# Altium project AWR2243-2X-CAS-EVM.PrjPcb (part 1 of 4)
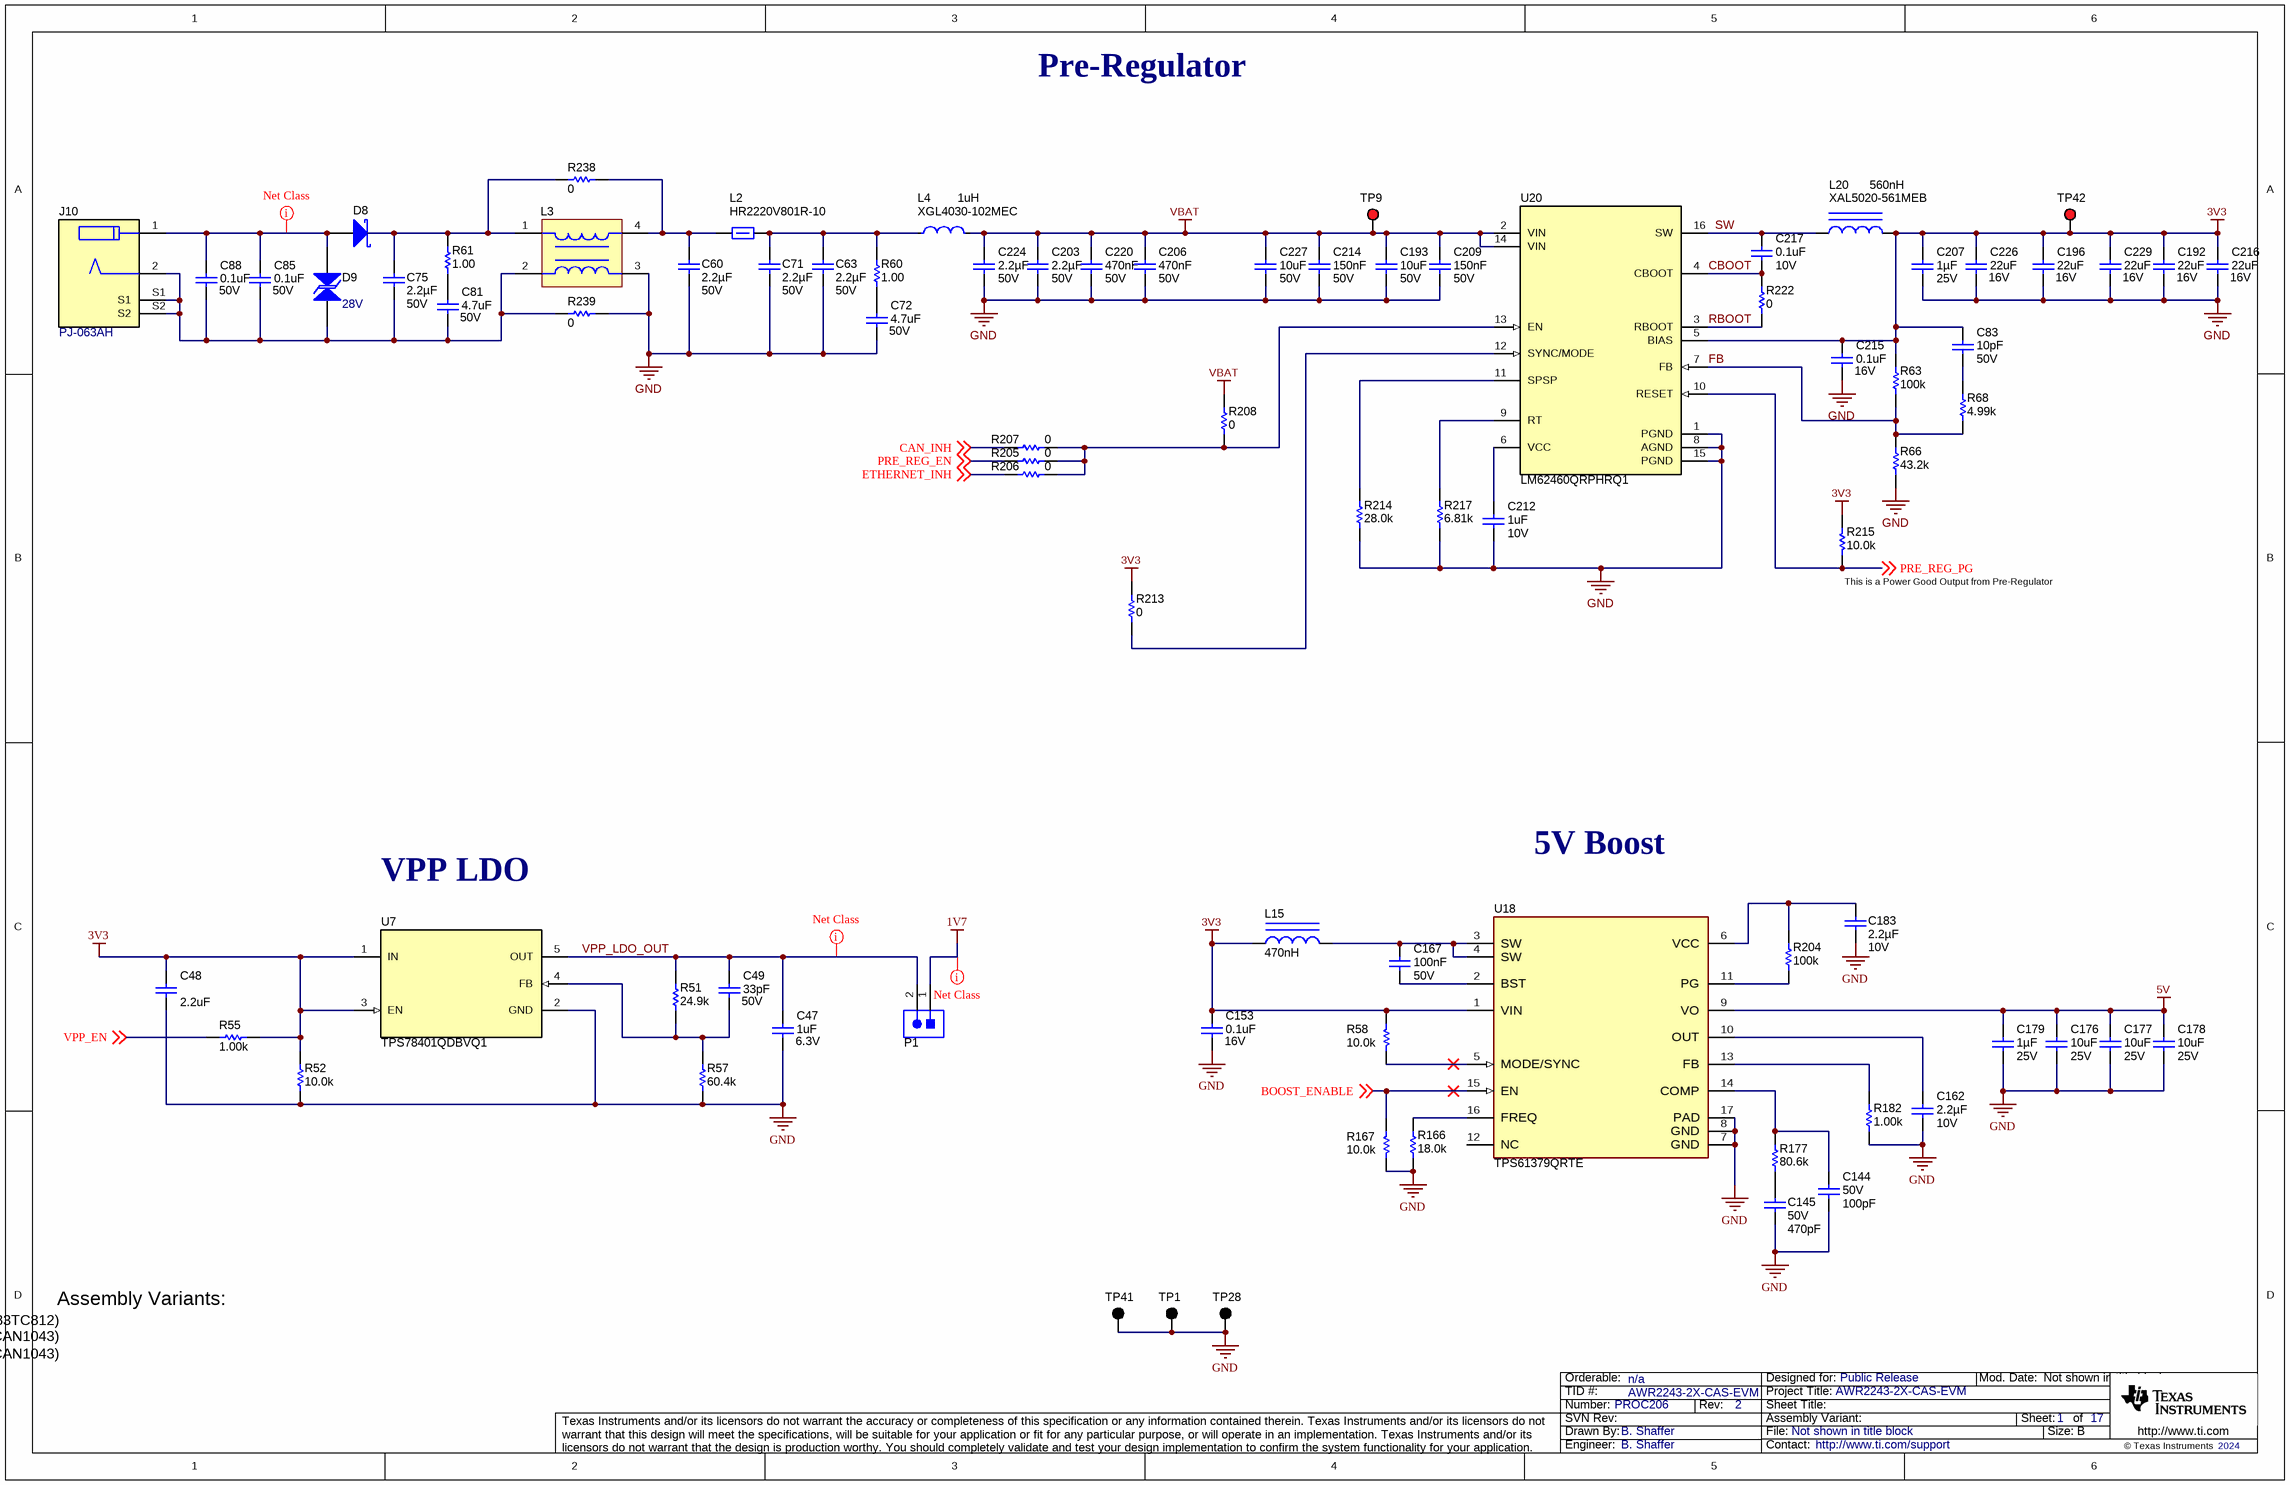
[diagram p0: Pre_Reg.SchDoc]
CopyrightYear: 2024; EVM_orderable: n/a; PCB_Layout: Krypton Solutions; PCB_Rev: C; PRJ_Customer: Public Release; PRJ_Engineer: B. Shaffer; PRJ_Number: PROC206; PRJ_Title: AWR2243-2X-CAS-EVM; SCH_Rev: 2; TechSupport: http://www.ti.com/support; TID: AWR2243-2X-CAS-EVM
17 sheets, 637 parts. Net scope: global (net labels, ports and power ports of the same name join across sheets).
Board file: AWR2243-2X-CAS-EVM.PcbDoc
Sheets:
  Pre_Reg.SchDoc
  PMIC.schdoc
  SOC_PWR.SchDoc
  SOC_IO.schdoc
  SOC_FLASH_SOP.SchDoc
  FE1_PWR.SchDoc
  FE1_IO.schdoc
  FE2_PWR.SchDoc
  FE2_IO.schdoc
  2CAN.SchDoc
  Enet_PHY.SchDoc
  Enet_Conn.SchDoc
  Temp.schdoc
  Connectors.schdoc
  Clock_Buff.SchDoc
  XDS110.schdoc
  Hardware.SchDoc

## Sheet Pre_Reg.SchDoc
size 431 x 279 mm; Date: Not shown in title block; ApprovedBy: Not shown in title block; CheckedBy: Not shown in title block; Author: Not shown in title block; CompanyName: Not shown in title block; DrawnBy: B. Shaffer; Engineer: Not shown in title block; Organization: Not shown in title block; Address1: Not shown in title block; Address2: Not shown in title block; Address3: Not shown in title block; Address4: Not shown in title block; DocumentNumber: 1; Revision: Use project parameter SCH_Rev; SheetNumber: 1; SheetTotal: 17; PageSetup: Record=PageOptions¦CenterHorizontal=True¦CenterVertical=True¦PrintScale=1.00¦XCorrection=1.00¦YCorrection=1.00¦PrintKind=0¦BorderSize=5000000¦LeftOffset=0¦BottomOffset=0¦Orientation=2¦PaperLength=1000¦PaperWidth=1000¦Scale=100¦PaperSource=15¦PrintQuality=600¦MediaType=1¦DitherType=10¦PaperKind=Letter¦PrintScaleMode=1

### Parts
C47  VDC_V: 6.3V  ValueDisplayed: 1uF  [0402]  (hidden comment: GRM155R70J105MA12D)
C48  ValueDisplayed: 2.2uF  [0402_065L]  (hidden comment: C1005X7S1A225K050BC)
C49  VDC_V: 50V  ValueDisplayed: 33pF  [0402L]  (hidden comment: C0402C330J5GAC)
C60  Cap_F: 2.2µF  VDC_V: 50V  [0805_HV]  (hidden comment: CGA4J3X7R1H225K125AB)
C63  Cap_F: 2.2µF  VDC_V: 50V  [0805_HV]  (hidden comment: CGA4J3X7R1H225K125AB)
C71  Cap_F: 2.2µF  VDC_V: 50V  [0805_HV]  (hidden comment: CGA4J3X7R1H225K125AB)
C72  VDC_V: 50V  ValueDisplayed: 4.7uF  [1206_180]  (hidden comment: C3216X7R1H475K160AC)
C75  Cap_F: 2.2µF  VDC_V: 50V  [0805_HV]  (hidden comment: CGA4J3X7R1H225K125AB)
C81  VDC_V: 50V  ValueDisplayed: 4.7uF  [1206_180]  (hidden comment: C3216X7R1H475K160AC)
C83  VDC_V: 50V  ValueDisplayed: 10pF  [0603]  (hidden comment: CGA3E2C0G1H100D080AA)
C85  VDC_V: 50V  ValueDisplayed: 0.1uF  [0603]  (hidden comment: CGA3E3X8R1H104K080AB)
C88  VDC_V: 50V  ValueDisplayed: 0.1uF  [0603]  (hidden comment: CGA3E3X8R1H104K080AB)
C144  VDC_V: 50V  ValueDisplayed: 100pF  [0402]  (hidden comment: 885012205055)
C145  VDC_V: 50V  ValueDisplayed: 470pF  [0402]  (hidden comment: GRM155R71H471KA01D)
C153  VDC_V: 16V  ValueDisplayed: 0.1uF  [0402L]  (hidden comment: GCM155R71C104KA55D)
C162  Cap_F: 2.2µF  VDC_V: 10V  [0603]  (hidden comment: GRM188R71A225KE15J)
C167  Cap_F: 100nF  VDC_V: 50V  [0603L]  (hidden comment: GCM188R71H104KA57D)
C176  VDC_V: 25V  ValueDisplayed: 10uF  [1210_280]  (hidden comment: GCM32ER71E106KA57L)
C177  VDC_V: 25V  ValueDisplayed: 10uF  [1210_280]  (hidden comment: GCM32ER71E106KA57L)
C178  VDC_V: 25V  ValueDisplayed: 10uF  [1210_280]  (hidden comment: GCM32ER71E106KA57L)
C179  Cap_F: 1µF  VDC_V: 25V  [0603L]  (hidden comment: GCM188R71E105KA64D)
C183  Cap_F: 2.2µF  VDC_V: 10V  [0603]  (hidden comment: GRM188R71A225KE15J)
C192  VDC_V: 16V  ValueDisplayed: 22uF  [1210_280]  (hidden comment: CO4)
C193  VDC_V: 50V  ValueDisplayed: 10uF  [1210_270]  (hidden comment: GRM32ER71H106KA12L)
C196  VDC_V: 16V  ValueDisplayed: 22uF  [1210_280]  (hidden comment: CO2)
C203  Cap_F: 2.2µF  VDC_V: 50V  [0805_HV]  (hidden comment: CGA4J3X7R1H225K125AB)
C206  Cap_F: 470nF  VDC_V: 50V  [0603]  (hidden comment: CGA3E3X7R1H474K080AE)
C207  Cap_F: 1µF  VDC_V: 25V  [0805_HV]  (hidden comment: CO5)
C209  Cap_F: 150nF  VDC_V: 50V  [0603]  (hidden comment: C1608X7R1H154K080AB)
C212  VDC_V: 10V  ValueDisplayed: 1uF  [0603]  (hidden comment: CBIAS)
C214  Cap_F: 150nF  VDC_V: 50V  [0603]  (hidden comment: C1608X7R1H154K080AB)
C215  VDC_V: 16V  ValueDisplayed: 0.1uF  [0402L]  (hidden comment: GCM155R71C104KA55D)
C216  VDC_V: 16V  ValueDisplayed: 22uF  [1210_280]  (hidden comment: CO4)
C217  VDC_V: 10V  ValueDisplayed: 0.1uF  [0603L]  (hidden comment: CBOOT)
C220  Cap_F: 470nF  VDC_V: 50V  [0603]  (hidden comment: CGA3E3X7R1H474K080AE)
C224  Cap_F: 2.2µF  VDC_V: 50V  [0805_HV]  (hidden comment: CGA4J3X7R1H225K125AB)
C226  VDC_V: 16V  ValueDisplayed: 22uF  [1210_280]  (hidden comment: CO1)
C227  VDC_V: 50V  ValueDisplayed: 10uF  [1210_270]  (hidden comment: GRM32ER71H106KA12L)
C229  VDC_V: 16V  ValueDisplayed: 22uF  [1210_280]  (hidden comment: CO3)
D8  FSV530AF  [SMAF]  (value not drawn)
D9  value 28V  [SOD-123]  (hidden comment: ATV02W280B-HF)
J10  PJ-063AH  [CUI_PJ-063AH]
L2  HR2220V801R-10  [2220_390]
L3  ACM1211-701-2PL-TL01  [TDK_ACM1211]  (value not drawn)
L4  value 1uH  [FP-XGL4030-102MEC_SMD_IND_4MM0_4MM0-MFG]  (hidden comment: XGL4030-102MEC)
L15  ValueDisplayed: 470nH  [XEL4030_310]  (hidden comment: XEL4030-471MEB)
L20  ValueDisplayed: 560nH  [XAL5020]  (hidden comment: XAL5020-561MEB)
P1  TSW-102-07-G-S  [TSW-102-07-G-S]  (value not drawn)
R51  ValueDisplayed: 24.9k  [0402]  (hidden comment: CRCW040224K9FKED)
R52  ValueDisplayed: 10.0k  [0402]  (hidden comment: ERJ-2RKF1002X)
R55  ValueDisplayed: 1.00k  [0603]  (hidden comment: RFF)
R57  ValueDisplayed: 60.4k  [0402]  (hidden comment: CRCW040260K4FKED)
R58  ValueDisplayed: 10.0k  [0402]  (hidden comment: CRCW040210K0FKED)
R60  ValueDisplayed: 1.00  [0402]  (hidden comment: CRCW04021R00FKED)
R61  ValueDisplayed: 1.00  [0402]  (hidden comment: CRCW04021R00FKED)
R63  ValueDisplayed: 100k  [0402]  (hidden comment: CRCW0402100KFKED)
R66  ValueDisplayed: 43.2k  [0402]  (hidden comment: CRCW040243K2FKED)
R68  ValueDisplayed: 4.99k  [0402]  (hidden comment: CRCW04024K99FKED)
R166  ValueDisplayed: 18.0k  [0402]  (hidden comment: CRCW040218K0FKED)
R167  ValueDisplayed: 10.0k  [0402]  (hidden comment: CRCW040210K0FKED)
R177  ValueDisplayed: 80.6k  [0402]  (hidden comment: CRCW040280K6FKED)
R182  ValueDisplayed: 1.00k  [0402]  (hidden comment: CRCW04021K00FKED)
R204  ValueDisplayed: 100k  [0402]  (hidden comment: CRCW0402100KFKED)
R205  ValueDisplayed: 0  [0402]  (hidden comment: CRCW04020000Z0ED)
R206  ValueDisplayed: 0  [0402]  (hidden comment: CRCW04020000Z0ED)
R207  ValueDisplayed: 0  [0402]  (hidden comment: CRCW04020000Z0ED)
R208  ValueDisplayed: 0  [0402]  (hidden comment: CRCW04020000Z0ED)
R213  ValueDisplayed: 0  [0402]  (hidden comment: CRCW04020000Z0ED)
R214  ValueDisplayed: 28.0k  [0402]  (hidden comment: CRCW040228K0FKED)
R215  ValueDisplayed: 10.0k  [0402]  (hidden comment: CRCW040210K0FKED)
R217  ValueDisplayed: 6.81k  [0402]  (hidden comment: CRCW04026K81FKED)
R222  ValueDisplayed: 0  [0402]  (hidden comment: CRCW04020000Z0ED)
R238  ValueDisplayed: 0  [1206]  (hidden comment: CRCW12060000Z0EAHP)
R239  ValueDisplayed: 0  [1206]  (hidden comment: CRCW12060000Z0EAHP)
TP1  5001  [Keystone5001]  (value not drawn)
TP9  5000  [Keystone5000]  (value not drawn)
TP28  5001  [Keystone5001]  (value not drawn)
TP41  5001  [Keystone5001]  (value not drawn)
TP42  5000  [Keystone5000]  (value not drawn)
U7  TPS78401QDBVQ1  [DBV0005A_N]
U18  TPS61379QRTE  [RTE0016K-MFG]
U20  LM62460QRPHRQ1  [RPH0016A]

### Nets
1V7: P1.1
3V3: C48.2 C83.1 C153.2 C192.1 C196.1 C207.1 C215.2 C216.1 C226.1 C229.1 L15.1 L20.2 R52.2 R55.1 R58.2 R63.2 R213.1 R215.2 TP42.1 U7.1(IN) U7.3(EN) U18.1(VIN) U20.5(BIAS)
5V: C176.1 C177.1 C178.1 C179.1 U18.9(VO)
GND: C47.2 C48.1 C60.2 C63.2 C71.2 C72.2 C144.2 C145.2 C153.1 C162.2 C176.2 C177.2 C178.2 C179.2 C183.2 C192.2 C193.2 C196.2 C203.2 C206.2 C207.2 C209.2 C212.1 C214.2 C215.1 C216.2 C220.2 C224.2 C226.2 C227.2 C229.2 L3.3 R52.1 R57.1 R66.1 R166.1 R167.1 R182.2 R214.1 R217.1 R239.2 TP1.1 TP28.1 TP41.1 U7.2(GND) U18.7(GND) U18.8(GND) U18.17(PAD) U20.1(PGND) U20.8(AGND) U20.15(PGND)
VBAT: C193.1 C203.1 C206.1 C209.1 C214.1 C220.1 C224.1 C227.1 L4.2 R208.1 TP9.1 U20.2(VIN) U20.14(VIN)
BOOST_ENABLE: R167.2 U18.15(EN) ; off-sheet BOOST_ENABLE
CAN_INH: R207.2 ; off-sheet CAN_INH
CBOOT: C217.2 R222.1 U20.4(CBOOT)
ETHERNET_INH: R206.2 ; off-sheet ETHERNET_INH
FB: R63.1 R66.2 R68.1 U20.7(FB)
PRE_REG_EN: R205.2 ; off-sheet PRE_REG_EN
PRE_REG_PG: R215.1 U20.10(RESET) ; off-sheet PRE_REG_PG
RBOOT: R222.2 U20.3(RBOOT)
SW: C217.1 L20.1 U20.16(SW)
VPP_EN: R55.2 ; off-sheet VPP_EN
VPP_LDO_OUT: C47.1 C49.1 P1.2 R51.2 U7.5(OUT)
NetC49_2: C49.2 R51.1 R57.2 U7.4(FB)
NetC60_1: C60.1 L2.1 L3.4 R238.2
NetC63_1: C63.1 C71.1 L2.2 L4.1 R60.2
NetC72_1: C72.1 R60.1
NetC75_1: C75.1 D8.1(K) L3.1 R61.2 R238.1
NetC75_2: C75.2 C81.2 C85.2 C88.2 D9.1 J10.2 J10.S1 J10.S2 L3.2 R239.1
NetC81_1: C81.1 R61.1
NetC83_2: C83.2 R68.2
NetC85_1: C85.1 C88.1 D8.2(A) D9.2 J10.1
NetC144_1: C144.1 R177.2 U18.14(COMP)
NetC145_1: C145.1 R177.1
NetC162_1: C162.1 U18.10(OUT)
NetC167_1: C167.1 L15.2 U18.3(SW) U18.4(SW)
NetC167_2: C167.2 U18.2(BST)
NetC183_1: C183.1 R204.2 U18.6(VCC)
NetC212_2: C212.2 U20.6(VCC)
NetR58_1: R58.1 U18.5(MODE/SYNC)
NetR166_2: R166.2 U18.16(FREQ)
NetR182_1: R182.1 U18.13(FB)
NetR204_1: R204.1 U18.11(PG)
NetR205_1: R205.1 R206.1 R207.1 R208.2 U20.13(EN)
NetR213_2: R213.2 U20.12(SYNC/MODE)
NetR214_2: R214.2 U20.11(SPSP)
NetR217_2: R217.2 U20.9(RT)

Not connected (* = marked no-connect by the designer): U18 12(NC)

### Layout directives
net class PWR: 1V7, NetC85_1, VPP_LDO_OUT

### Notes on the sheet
- Pre-Regulator
- (near R215) This is a Power Good Output from Pre-Regulator
- VPP LDO
- 5V Boost
- Assembly Variants:
- 812: DP83TC812 Ethernet and CAN present.  WAKE Controlled by Ethernet (DP83TC812)
- CAN: DP83TC812 Ethernet and CAN present.  WAKE Controlled by CAN (TCAN1043)
- 811: DP83TC811 Ethernet and CAN present.  WAKE Controlled by CAN (TCAN1043)

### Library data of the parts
C47 = CMP-0006624-2: CAP, CERM, 1 uF, 6.3 V, +/- 20%, X7R, 0402; Manufacturer: MuRata; TaMin_C: -55°C; Polarized: N; SizeAreaWB_mm2: 3; Value1: Unknown; U/M: EA; Value: 1uF; TaMax_C: 125°C; SizeZ_mm: 0.6; SizeX_mm: 1; SizeY_mm: 0.5; CompType: Capacitor; Cap_F: 1µF; AEC Category: Q200
C48 = CMP-0006302-2: CAP, CERM, 2.2 uF, 10 V, +/- 10%, X7S, 0402; Manufacturer: TDK; TaMin_C: -55°C; ESR_ohm: 5.925m; Polarized: N; SizeAreaWB_mm2: 3; Value1: 0.005925 ohm; U/M: EA; Value: 2.2uF; TaMax_C: 125°C; SizeZ_mm: 0.65; SizeX_mm: 1; SizeY_mm: 0.5; Cap_Case: 0402_065; Value2: 10V; CompType: Capacitor; Cap_F: 2.2µF; IRMS_A: 2.05591A; AEC Category: Q200
C49 = CMP-0006242-2: CAP, CERM, 33 pF, 50 V, +/- 5%, C0G/NP0, 0402; Manufacturer: Kemet; TaMin_C: -55°C; Polarized: N; SizeAreaWB_mm2: 3; Value1: Unknown; U/M: EA; Value: 33pF; TaMax_C: 125°C; SizeZ_mm: 0.6; SizeX_mm: 1; SizeY_mm: 0.5; Cap_Case: 0402; CompType: Capacitor; AEC Category: Q200
C60 C63 C71 C75 C203 C224 = CMP-0007977-2: CAP, CERM, 2.2 uF, 50 V, +/- 10%, X7R, AEC-Q200 Grade 1, 0805; Manufacturer: TDK; TaMin_C: -55°C; ESR_ohm: 3.288m; Polarized: N; SizeAreaWB_mm2: 6.75; Value1: 0.003288 ohm; U/M: EA; Value: 2.2uF; TaMax_C: 125°C; SizeZ_mm: 1.45; SizeX_mm: 2; SizeY_mm: 1.25; Cap_Case: 0805; SizeArea_mm2: 2.5; AEC Qualified: Y; IRMS_A: 3.60029A; AEC Grade: 1; AEC Category: Q200
C72 C81 = CMP-0008702-2: CAP, CERM, 4.7 uF, 50 V, +/- 10%, X7R, 1206; Manufacturer: TDK; TaMin_C: -55°C; ESR_ohm: 3.158m; Polarized: N; SizeAreaWB_mm2: 10.92; Value1: 0.003158 ohm; U/M: EA; Value: 4.7uF; TaMax_C: 125°C; SizeZ_mm: 1.8; SizeX_mm: 3.2; SizeY_mm: 1.6; SizeArea_mm2: 5.12; CompType: Capacitor; Cap_F: 4.7µF; IRMS_A: 4.08379A; AEC Category: Q200
C83 = CMP-0007069-4: CAP, CERM, 10 pF, 50 V, +/- 5%, C0G/NP0, AEC-Q200 Grade 1, 0603; Manufacturer: TDK; TaMin_C: -55°C; Polarized: N; SizeAreaWB_mm2: 4.68; Value1: Unknown; U/M: EA; Value: 10pF; TaMax_C: 125°C; SizeZ_mm: 1; SizeX_mm: 1.6; SizeY_mm: 0.8; SizeArea_mm2: 1.28; AEC Qualified: Y; AEC Category: Q200
C85 C88 = CMP-0007104-4: CAP, CERM, 0.1 uF, 50 V, +/- 10%, X8R, AEC-Q200 Grade 0, 0603; Manufacturer: TDK; TaMin_C: -55°C; Polarized: N; SizeAreaWB_mm2: 4.68; Value1: Unknown; U/M: EA; Value: 0.1uF; TaMax_C: 150°C; SizeZ_mm: 1; SizeX_mm: 1.6; SizeY_mm: 0.8; SizeArea_mm2: 1.28; CompType: Capacitor; AEC Qualified: Y; Cap_F: 100nF; AEC Grade: 0; AEC Category: Q200
C144 = CMP-0006230-1: CAP, CERM, 100 pF, 50 V, +/- 10%, X7R, 0402; Manufacturer: Wurth Elektronik; TaMin_C: -55°C; Polarized: N; SizeAreaWB_mm2: 3; Value1: Unknown; U/M: EA; Value: 100pF; TaMax_C: 125°C; SizeZ_mm: 0.6; SizeX_mm: 1; SizeY_mm: 0.5; AEC Category: Q200
C145 = CMP-0006691-2: CAP, CERM, 470 pF, 50 V, +/- 10%, X7R, 0402; Manufacturer: MuRata; TaMin_C: -55°C; Polarized: N; SizeAreaWB_mm2: 3; Value1: Unknown; U/M: EA; Value: 470pF; TaMax_C: 125°C; SizeZ_mm: 0.6; SizeX_mm: 1; SizeY_mm: 0.5; AEC Category: Q200
C153 C215 = CMP-0006351-2: CAP, CERM, 0.1 uF, 16 V, +/- 10%, X7R, 0402; Manufacturer: MuRata; TaMin_C: -55°C; Polarized: N; SizeAreaWB_mm2: 3; Value1: Unknown; U/M: EA; Value: 0.1uF; TaMax_C: 125°C; SizeZ_mm: 0.6; SizeX_mm: 1; SizeY_mm: 0.5; Cap_Case: 0402; CompType: Capacitor; Cap_F: 100nF; AEC Category: Q200
C162 C183 = CMP-0084284-1: CAP, CERM, 2.2 µF, 10 V,+/- 10%, X7R, AEC-Q200 Grade 1, 0603; Manufacturer: MuRata; SizeAreaWB_mm2: 4.68; Polarized: N; AEC Qualified: Y; SizeX_mm: 1.6; SizeZ_mm: 1; SizeY_mm: 0.8; U/M: EA; TaMin_C: -55°C; Value: 2.2uF; AEC Category: Q200; TaMax_C: 125°C; SizeArea_mm2: 1.28
C167 = CMP-0007144-4: CAP, CERM, 0.1 uF, 50 V, +/- 10%, X7R, 0603; Manufacturer: MuRata; TaMin_C: -55°C; ESR_ohm: 0.02; Polarized: N; SizeAreaWB_mm2: 4.68; Value1: 0.02 ohm; U/M: EA; Value: 0.1uF; TaMax_C: 125°C; SizeZ_mm: 1; SizeX_mm: 1.6; SizeY_mm: 0.8; Cap_Case: 0603; SizeArea_mm2: 1.28; CompType: Capacitor; IRMS_A: 1.84A; AEC Category: Q200
C176-C178 = CMP-0009175-2: CAP, CERM, 10 uF, 25 V, +/- 10%, X7R, AEC-Q200 Grade 1, 1210; Manufacturer: MuRata; TaMin_C: -55°C; Polarized: N; SizeAreaWB_mm2: 14.7; Value1: Unknown; U/M: EA; Value: 10uF; TaMax_C: 125°C; SizeZ_mm: 2.8; SizeX_mm: 3.2; SizeY_mm: 2.5; Cap_Case: 1210; SizeArea_mm2: 8; AEC Qualified: Y; Cap_F: 10µF; AEC Grade: 1; AEC Category: Q200
C179 = CMP-0007139-4: CAP, CERM, 1 uF, 25 V, +/- 10%, X7R, AEC-Q200 Grade 1, 0603; Manufacturer: MuRata; TaMin_C: -55°C; Polarized: N; SizeAreaWB_mm2: 4.68; Value1: Unknown; U/M: EA; Value: 1uF; TaMax_C: 125°C; SizeZ_mm: 1; SizeX_mm: 1.6; SizeY_mm: 0.8; Cap_Case: 0603; SizeArea_mm2: 1.28; AEC Qualified: Y; AEC Category: Q200
C192 C196 C216 = CMP-0009154-2: CAP, CERM, 22 uF, 16 V, +/- 20%, X7R, AEC-Q200 Grade 1, 1210; Manufacturer: TDK; PartNumber: CGA6P1X7R1C226M250AC; TaMin_C: -55°C; ESR_ohm: 2.582m; Polarized: N; SizeAreaWB_mm2: 14.7; Value1: 0.002582 ohm; U/M: EA; Value: 22uF; TaMax_C: 125°C; SizeZ_mm: 2.8; SizeX_mm: 3.2; SizeY_mm: 2.5; SizeArea_mm2: 8; CompType: Capacitor; AEC Qualified: Y; Cap_F: 22µF; IRMS_A: 4.57562A; AEC Grade: 1; AEC Category: Q200
C193 C227 = CMP-0009226-3: CAP, CERM, 10 uF, 50 V, +/- 10%, X7R, 1210; Manufacturer: MuRata; TaMin_C: -55°C; Polarized: N; SizeAreaWB_mm2: 14.7; Value1: Unknown; U/M: EA; Value: 10uF; TaMax_C: 125°C; SizeZ_mm: 2.7; SizeX_mm: 3.2; SizeY_mm: 2.5; Cap_Case: 1210; SizeArea_mm2: 8; Cap_F: 10µF; AEC Category: Q200
C206 C220 = CMP-0007097-4: CAP, CERM, 0.47 uF, 50 V, +/- 10%, X7R, AEC-Q200 Grade 1, 0603; Manufacturer: TDK; TaMin_C: -55°C; Polarized: N; SizeAreaWB_mm2: 4.68; Value1: Unknown; U/M: EA; Value: 0.47uF; TaMax_C: 125°C; SizeZ_mm: 1; SizeX_mm: 1.6; SizeY_mm: 0.8; SizeArea_mm2: 1.28; AEC Qualified: Y; AEC Category: Q200
C207 = CMP-0007728-2: CAP, CERM, 1 uF, 25 V, +/- 10%, X7R, 0805; Manufacturer: Kemet; PartNumber: C0805C105K3RACTU; TaMin_C: -55°C; Polarized: N; SizeAreaWB_mm2: 6.75; Value1: Unknown; U/M: EA; Value: 1uF; TaMax_C: 125°C; SizeZ_mm: 1.45; SizeX_mm: 2; SizeY_mm: 1.25; Cap_Case: 0805; SizeArea_mm2: 2.5; CompType: Capacitor; AEC Category: Q200
C209 C214 = CMP-0007046-5: CAP, CERM, 0.15 uF, 50 V, +/- 10%, X7R, 0603; Manufacturer: TDK; TaMin_C: -55°C; ESR_ohm: 0.028863; Polarized: N; SizeAreaWB_mm2: 4.68; Value1: 0.028863 ohm; U/M: EA; Value: 0.15uF; TaMax_C: 125°C; SizeZ_mm: 1; SizeX_mm: 1.6; SizeY_mm: 0.8; SizeArea_mm2: 1.28; IRMS_A: 9.78809dA; AEC Category: Q200
C212 = CMP-0007365-4: CAP, CERM, 1 uF, 10 V, +/- 10%, X7R, 0603; Manufacturer: MuRata; PartNumber: GRM188R71A105KA61D; TaMin_C: -55°C; ESR_ohm: 0.011; Polarized: N; SizeAreaWB_mm2: 4.68; Value1: 0.011 ohm; U/M: EA; Value: 1uF; TaMax_C: 125°C; SizeZ_mm: 1; SizeX_mm: 1.6; SizeY_mm: 0.8; SizeArea_mm2: 1.28; CompType: Capacitor; Cap_F: 1µF; AEC Category: Q200
C217 = CMP-0006981-4: CAP, CERM, 0.1 uF, 10 V, +/- 10%, X7R, 0603; Manufacturer: Kemet; PartNumber: C0603X104K8RACTU; TaMin_C: -55°C; Polarized: N; SizeAreaWB_mm2: 4.68; Value1: Unknown; U/M: EA; Value: 0.1uF; TaMax_C: 125°C; SizeZ_mm: 1; SizeX_mm: 1.6; Cap_Case: 0603; SizeArea_mm2: 1.28; CompType: Capacitor; Cap_F: 100nF; AEC Category: Q200; SizeY_mm: 0.8
C226 = CMP-0009154-2: CAP, CERM, 22 uF, 16 V, +/- 20%, X7R, AEC-Q200 Grade 1, 1210; Manufacturer: TDK; PartNumber: CGA6P1X7R1C226M250AC; TaMin_C: -55°C; Polarized: N; SizeAreaWB_mm2: 14.7; Value1: 0.002582 ohm; U/M: EA; Value: 22uF; TaMax_C: 125°C; SizeZ_mm: 2.8; SizeX_mm: 3.2; SizeY_mm: 2.5; SizeArea_mm2: 8; CompType: Capacitor; AEC Qualified: Y; Cap_F: 22µF; AEC Category: Q200; AEC Grade: 1; ESR_ohm: 2.582m; IRMS_A: 4.57562A
C229 = CMP-0009154-2: CAP, CERM, 22 uF, 16 V, +/- 20%, X7R, AEC-Q200 Grade 1, 1210; Manufacturer: TDK; PartNumber: CGA6P1X7R1C226M250AC; TaMin_C: -55°C; Polarized: N; SizeAreaWB_mm2: 14.7; U/M: EA; Value: 22uF; TaMax_C: 125°C; SizeZ_mm: 2.8; SizeX_mm: 3.2; SizeY_mm: 2.5; SizeArea_mm2: 8; CompType: Capacitor; AEC Qualified: Y; Cap_F: 22µF; AEC Grade: 1; AEC Category: Q200; ESR_ohm: 2.582m; IRMS_A: 4.57562A; Value1: 0.002582 ohm
D8 = CMP-0028823-2: Diode, Schottky, 30 V, 5 A, AEC-Q101, SMAF; Manufacturer: Fairchild Semiconductor; Io_A: 5A; Vr_V: 30V; SizeY_mm: 2.5; Green_REACh: Incomplete; SizeArea_mm2: 11.75; SizeZ_mm: 1; AEC Category: Q101; Vf_V: 540mV; AEC Qualified: Y; SizeAreaWB_mm2: 19.95; Green_Lifecycle: Not Set; SizeX_mm: 4.7; Value: 30V; Value2: 0.54V; TJmax_C: 150°C
D9 = CMP-0005735-3: Diode, TVS, Bi, 28 V, 45.4 Vc, AEC-Q101, SOD-123; Manufacturer: Comchip Technology; SizeAreaWB_mm2: 13.095; Value1: 200W; SizeZ_mm: 1.35; SizeX_mm: 3.85; SizeY_mm: 1.7; SizeArea_mm2: 6.545; AEC Qualified: Y; AEC Category: Q101; Ipp: 4.41A; Vbr_Max: 34.4V; Vbr_Min: 31.1V; Vc: 45.4V
J10 = CMP-0079472-1: DC POWER JACK, R/A, TH; Manufacturer: CUI Inc.; Gender: Male; Cert_UL: Y; Current_A: 8A; Voltage_V: 24V
L2 = CMP-0003396-1: Ferrite Bead, 800 ohm @ 100 MHz, 8 A, 2220; Manufacturer: Laird-Signal Integrity Products; Ztyp@1GHz_Ohm: 75; ZTyp@100MHz_Ohm: 800; SizeAreaWB_mm2: 53.96; DCR_ohm: 0.01; Value1: 0.01 ohm; Value: 800 ohm; Imax_A: 8A; SizeZ_mm: 3.9; SizeX_mm: 5.6; SizeY_mm: 5.1; SizeArea_mm2: 28.56
L3 = CMP-0013118-2: Coupled inductor, 8 A, 0.006 ohm, SMD; Manufacturer: TDK; DCR_ohm: 6m
L4 = CMP-0090842-1: Power Inductor, shielded, composite, 1uH 20% tol, DCR 7.2mOhms, SRF 65MHz, Isat 4.8A, Irms 13A, AEC-Q200; Manufacturer: Coilcraft; TaMin_C: -40°C; TaMax_C: +125°C; Test Frequency: 1MHz; DCR_ohm: 7.2m; AEC Grade: Grade 1; SizeZ_mm: 3.1mm; AEC Qualified: Yes; Shrouded: true; Ind_H: 1µH
L15 = CMP-0061091-1: Inductor, Shielded, Composite, 470 nH, 15.5 A, 0.0041 ohm, AEC-Q200 Grade 1, SMD; Manufacturer: Coilcraft; Isat: 15.5A @ 30% inductance drop; Irms: 15.6A @ 40C rise; SizeAreaWB_mm2: 25; DCR_ohm: 4.1m; Value: 470nH; Imax_A: 15.5A; SizeZ_mm: 3.1; SizeX_mm: 4; SizeArea_mm2: 16; AEC Qualified: Y; AEC Grade: 1; AEC Category: Q200
L20 = CMP-0060997-1: Inductor, Shielded, Composite, 560 nH, 13.9 A, 0.0083 ohm, AEC-Q200 Grade 1, SMD; Manufacturer: Coilcraft; Isat: 14.1A @ 30% inductance drop; Irms: 13.9A @ 40C rise; Green_Lifecycle: Not Set; SizeAreaWB_mm2: 54.4544; DCR_ohm: 8.3m; Green_REACh: Incomplete; Value: 560nH; Imax_A: 13.9A; SizeZ_mm: 2; SizeX_mm: 5.28; SizeY_mm: 5.48; SizeArea_mm2: 28.9344; AEC Qualified: Y; AEC Grade: 1; AEC Category: Q200
P1 = CMP-0075405-3: Header, 100mil, 2x1, Gold, TH; Manufacturer: Samtec; Pitch_mm: 2.54; Cert_VDE: N; Gender: Male; Cert_CSA: Y; Voltage_V: 550V; Green_REACh: Passed; Current_A: 6.3A; Green_Lifecycle: Active; Row_Count: 1
R51 = CMP-0026196-2: RES, 24.9 k, 1%, 0.063 W, AEC-Q200 Grade 0, 0402; Manufacturer: Vishay-Dale; Power_W: 63mW; TempCo: 100 ppm/C; Value_Code: 24k9; Value: 24.9k; EIA_Code: E96; SizeX_mm: 1; SizeY_mm: 0.5; SizeZ_mm: 0.6; Value2: 0.063W; AEC Qualified: Y; VDC_V: 50V; AEC Category: Q200; AEC Grade: 0
R52 = CMP-0026658-1: RES, 10.0 k, 1%, 0.1 W, 0402; Manufacturer: Panasonic; Power_W: 100mW; TempCo: 100 ppm/C; Value_Code: 10k0; U/M: EA; Value: 10.0k; EIA_Code: E96; Res_ohm: 10k; SizeX_mm: 1; SizeY_mm: 0.5; SizeZ_mm: 0.6; Value2: 0.1W; VDC_V: 50V; AEC Category: Q200
R55 = CMP-0022680-4: RES, 1.00 k, 1%, 0.1 W, 0603; Manufacturer: Panasonic; PartNumber: ERJ-3EKF1001V; Power_W: 100mW; TempCo: 100 ppm/C; Value_Code: 1k00; U/M: EA; Value: 1.00k; EIA_Code: E96; Res_ohm: 1k; SizeX_mm: 1.6; SizeY_mm: 0.8; SizeZ_mm: 1; Value2: 0.1W; SizeArea_mm2: 1.28; CompType: Resistor; VDC_V: 75V; AEC Category: Q200
R57 = CMP-0026486-2: RES, 60.4 k, 1%, 0.063 W, AEC-Q200 Grade 0, 0402; Manufacturer: Vishay-Dale; Power_W: 63mW; TempCo: 100 ppm/C; Value_Code: 60k4; Value: 60.4k; EIA_Code: E96; SizeX_mm: 1; SizeY_mm: 0.5; SizeZ_mm: 0.6; Value2: 0.063W; AEC Qualified: Y; VDC_V: 50V; AEC Category: Q200; AEC Grade: 0
R58 R167 R215 = CMP-0025958-3: RES, 10.0 k, 1%, 0.063 W, AEC-Q200 Grade 0, 0402; Manufacturer: Vishay-Dale; Power_W: 63mW; TempCo: 100 ppm/C; Value_Code: 10k0; Value: 10.0k; EIA_Code: E96; Res_ohm: 10k; SizeX_mm: 1; SizeY_mm: 0.5; SizeZ_mm: 0.6; Value2: 0.063W; CompType: Resistor; AEC Qualified: Y; VDC_V: 50V; AEC Category: Q200; AEC Grade: 0; INSTALLATION: DNP
R60 R61 = CMP-0026129-2: RES, 1.00, 1%, 0.063 W, AEC-Q200 Grade 0, 0402; Manufacturer: Vishay-Dale; Power_W: 63mW; TempCo: 100 ppm/C; Value_Code: 1R00; Value: 1.00; EIA_Code: E96; Res_ohm: 1; SizeY_mm: 0.5; SizeZ_mm: 0.6; Value2: 0.063W; AEC Qualified: Y; VDC_V: 50V; AEC Category: Q200; AEC Grade: 0
R63 R204 = CMP-0025950-3: RES, 100 k, 1%, 0.063 W, AEC-Q200 Grade 0, 0402; Manufacturer: Vishay-Dale; Power_W: 63mW; TempCo: 100 ppm/C; Value: 100k; EIA_Code: E96; SizeX_mm: 1; SizeY_mm: 0.5; SizeZ_mm: 0.6; Value2: 0.063W; AEC Qualified: Y; VDC_V: 50V; AEC Category: Q200; AEC Grade: 0
R66 = CMP-0026379-2: RES, 43.2 k, 1%, 0.063 W, AEC-Q200 Grade 0, 0402; Manufacturer: Vishay-Dale; Power_W: 63mW; TempCo: 100 ppm/C; Value_Code: 43k2; Value: 43.2k; EIA_Code: E96; SizeX_mm: 1; SizeY_mm: 0.5; SizeZ_mm: 0.6; Value2: 0.063W; AEC Qualified: Y; VDC_V: 50V; AEC Category: Q200; AEC Grade: 0
R68 = CMP-0026414-2: RES, 4.99 k, 1%, 0.063 W, AEC-Q200 Grade 0, 0402; Manufacturer: Vishay-Dale; Power_W: 63mW; TempCo: 100 ppm/C; Value_Code: 4k99; Value: 4.99k; EIA_Code: E96; SizeX_mm: 1; SizeY_mm: 0.5; SizeZ_mm: 0.6; Value2: 0.063W; AEC Qualified: Y; VDC_V: 50V; AEC Category: Q200; AEC Grade: 0
R166 = CMP-0026058-3: RES, 18.0 k, 1%, 0.063 W, AEC-Q200 Grade 0, 0402; Manufacturer: Vishay-Dale; Power_W: 63mW; TempCo: 100 ppm/C; Value_Code: 18k0; Value: 18.0k; Res_ohm: 18k; SizeX_mm: 1; SizeY_mm: 0.5; SizeZ_mm: 0.6; Value2: 0.063W; AEC Qualified: Y; VDC_V: 50V; AEC Grade: 0; AEC Category: Q200
R177 = CMP-0026570-2: RES, 80.6 k, 1%, 0.063 W, AEC-Q200 Grade 0, 0402; Manufacturer: Vishay-Dale; Power_W: 63mW; TempCo: 100 ppm/C; Value_Code: 80k6; Value: 80.6k; EIA_Code: E96; SizeX_mm: 1; SizeY_mm: 0.5; SizeZ_mm: 0.6; Value2: 0.063W; AEC Qualified: Y; VDC_V: 50V; AEC Category: Q200; AEC Grade: 0
R182 = CMP-0026071-3: RES, 1.00 k, 1%, 0.063 W, AEC-Q200 Grade 0, 0402; Manufacturer: Vishay-Dale; Power_W: 63mW; TempCo: 100 ppm/C; Value_Code: 1k00; Value: 1.00k; EIA_Code: E96; Res_ohm: 1k; SizeX_mm: 1; SizeY_mm: 0.5; SizeZ_mm: 0.6; Value2: 0.063W; AEC Qualified: Y; VDC_V: 50V; AEC Category: Q200; AEC Grade: 0
R205-R208 R213 R222 = CMP-0026822-3: RES, 0, 5%, 0.063 W, AEC-Q200 Grade 0, 0402; Manufacturer: Vishay-Dale; Power_W: 63mW; TempCo: 200 ppm/C; Value_Code: 0000; Value: 0; EIA_Code: E24; SizeX_mm: 1; SizeY_mm: 0.5; SizeZ_mm: 0.6; Value2: 0.063W; AEC Qualified: Y; VDC_V: 50V; AEC Category: Q200
R214 = CMP-0026219-2: RES, 28.0 k, 1%, 0.063 W, AEC-Q200 Grade 0, 0402; Manufacturer: Vishay-Dale; Power_W: 63mW; TempCo: 100 ppm/C; Value_Code: 28k0; Value: 28.0k; EIA_Code: E96; Res_ohm: 28k; SizeX_mm: 1; SizeY_mm: 0.5; SizeZ_mm: 0.6; Value2: 0.063W; AEC Qualified: Y; VDC_V: 50V; AEC Category: Q200; AEC Grade: 0
R217 = CMP-0026517-2: RES, 6.81 k, 1%, 0.063 W, AEC-Q200 Grade 0, 0402; Manufacturer: Vishay-Dale; Power_W: 63mW; TempCo: 100 ppm/C; Value_Code: 6k81; Value: 6.81k; EIA_Code: E96; SizeX_mm: 1; SizeY_mm: 0.5; SizeZ_mm: 0.6; Value2: 0.063W; AEC Qualified: Y; VDC_V: 50V; AEC Category: Q200; AEC Grade: 0
R238 R239 = CMP-0086176-1: RES, 0, 0.75 W, AEC-Q200 Grade 0, 1206; Manufacturer: Vishay-Dale; Value: 0; SizeY_mm: 1.6; SizeX_mm: 3.2; Tolerance_%: 0%; SizeArea_mm2: 5.12; EIA_Code: E96; SizeAreaWB_mm2: 10.92; Power_W: 750mW; AEC Qualified: Y; SizeZ_mm: 1.35; Value2: 0.75W; AEC Category: Q200; VDC_V: 200V
TP1 TP28 TP41 = 5001: Test Point, Miniature, Black, TH; Manufacturer: Keystone; CompType: Test Point Loop; U/M: EA
TP9 TP42 = 5000: Test Point, Miniature, Red, TH; Manufacturer: Keystone; CompType: Test Point Loop; U/M: EA
U7 = CMP-0860753-1: 300-mA, Low-IQ Low-Dropout Regulator, DBV0005A (SOT-23-5); Alternate Manufacturer: Texas Instruments; SizeZ_mm: 1.45; AEC Qualified: Y; SizeAreaWB_mm2: 14.82; AEC Category: Q200; CompType: IC; SizeY_mm: 2.9; SizeX_mm: 2.8; SizeArea_mm2: 8.12
U18 = CMP-0089188-3: 25-µA Quiescent Current Synchronous Boost Converter with Load Disconnect; Manufacturer: Texas Instruments; Output Voltage: 3-18.5V; Standoff Height: 0mm; Number Of Outputs: 1; Max Supply Voltage: 14V; AEC Category: Q200; TaMin_C: -40°C; AEC Qualified: Yes; TJmax_C: +175°C; Min Supply Voltage: 2.3V; Nominal Supply Current: 25uA; AEC Grade: Grade 1; TaMax_C: +125°C; SizeZ_mm: 0.8mm; Output Type: AdjustableProgrammable; Switching Frequency: 200-2200kHz; CompType: IC
U20 = CMP-0860179-2: LM62460QRPHRQ1, RPH0016A (VQFN-HR-16); Manufacturer: Texas Instruments; SizeArea_mm2: 15.75; CompType: IC; SizeZ_mm: 1; SizeY_mm: 4.5; SizeAreaWB_mm2: 24.75; SizeX_mm: 3.5; AEC Category: Q200; AEC Qualified: Y

## Sheet PMIC.schdoc
size 431 x 279 mm; Date: Not shown in title block; ApprovedBy: Not shown in title block; CheckedBy: Not shown in title block; Author: Not shown in title block; CompanyName: Not shown in title block; DrawnBy: B. Shaffer; Engineer: Not shown in title block; Organization: Not shown in title block; Address1: Not shown in title block; Address2: Not shown in title block; Address3: Not shown in title block; Address4: Not shown in title block; DocumentNumber: 2; Revision: Use project parameter SCH_Rev; SheetNumber: 2; SheetTotal: 17; PageSetup: Record=PageOptions¦CenterHorizontal=True¦CenterVertical=True¦PrintScale=1.00¦XCorrection=1.00¦YCorrection=1.00¦PrintKind=0¦BorderSize=5000000¦LeftOffset=0¦BottomOffset=0¦Orientation=2¦PaperLength=1000¦PaperWidth=1000¦Scale=100¦PaperSource=15¦PrintQuality=600¦MediaType=1¦DitherType=10¦PaperKind=Letter¦PrintScaleMode=1
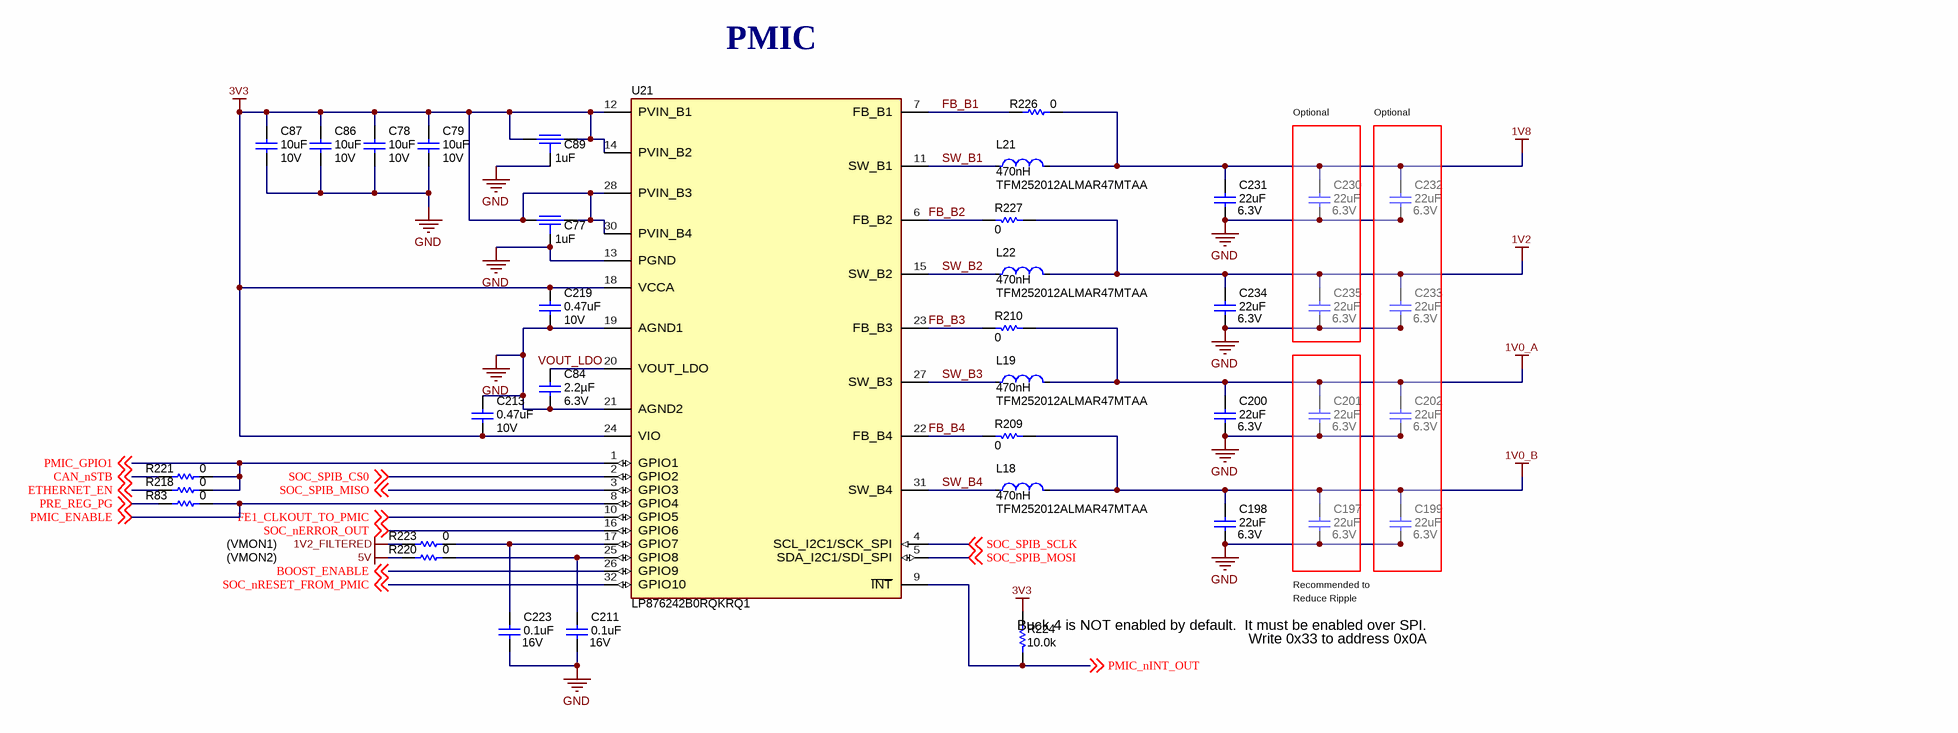
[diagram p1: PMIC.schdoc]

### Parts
C77  ValueDisplayed: 1uF  [FP-NFM18HC105C1C3D_0603-MFG]  (hidden comment: NFM18HC105C1C3D)
C78  VDC_V: 10V  ValueDisplayed: 10uF  [0805_HV]  (hidden comment: GCM21BR71A106KE22L)
C79  VDC_V: 10V  ValueDisplayed: 10uF  [0805_HV]  (hidden comment: GCM21BR71A106KE22L)
C84  Cap_F: 2.2µF  VDC_V: 6.3V  [0603S]  (hidden comment: GCM188R70J225KE22D)
C86  VDC_V: 10V  ValueDisplayed: 10uF  [0805_HV]  (hidden comment: GCM21BR71A106KE22L)
C87  VDC_V: 10V  ValueDisplayed: 10uF  [0805_HV]  (hidden comment: GCM21BR71A106KE22L)
C89  ValueDisplayed: 1uF  [FP-NFM18HC105C1C3D_0603-MFG]  (hidden comment: NFM18HC105C1C3D)
C197  VDC_V: 6.3V  ValueDisplayed: 22uF  [0805]  (hidden comment: GCM21BD70J226ME36L)
C198  VDC_V: 6.3V  ValueDisplayed: 22uF  [0805]  (hidden comment: GCM21BD70J226ME36L)
C199  VDC_V: 6.3V  ValueDisplayed: 22uF  [0805]  (hidden comment: GCM21BD70J226ME36L)
C200  VDC_V: 6.3V  ValueDisplayed: 22uF  [0805]  (hidden comment: GCM21BD70J226ME36L)
C201  VDC_V: 6.3V  ValueDisplayed: 22uF  [0805]  (hidden comment: GCM21BD70J226ME36L)
C202  VDC_V: 6.3V  ValueDisplayed: 22uF  [0805]  (hidden comment: GCM21BD70J226ME36L)
C211  VDC_V: 16V  ValueDisplayed: 0.1uF  [0402L]  (hidden comment: GCM155R71C104KA55D)
C213  VDC_V: 10V  ValueDisplayed: 0.47uF  [0402S]  (hidden comment: GCM155C71A474KE36D)
C219  VDC_V: 10V  ValueDisplayed: 0.47uF  [0402S]  (hidden comment: GCM155C71A474KE36D)
C223  VDC_V: 16V  ValueDisplayed: 0.1uF  [0402L]  (hidden comment: GCM155R71C104KA55D)
C230  VDC_V: 6.3V  ValueDisplayed: 22uF  [0805]  (hidden comment: GCM21BD70J226ME36L)
C231  VDC_V: 6.3V  ValueDisplayed: 22uF  [0805]  (hidden comment: GCM21BD70J226ME36L)
C232  VDC_V: 6.3V  ValueDisplayed: 22uF  [0805]  (hidden comment: GCM21BD70J226ME36L)
C233  VDC_V: 6.3V  ValueDisplayed: 22uF  [0805]  (hidden comment: GCM21BD70J226ME36L)
C234  VDC_V: 6.3V  ValueDisplayed: 22uF  [0805]  (hidden comment: GCM21BD70J226ME36L)
C235  VDC_V: 6.3V  ValueDisplayed: 22uF  [0805]  (hidden comment: GCM21BD70J226ME36L)
L18  Ind_H: 470nH  [FP-TFM252012ALMAR47MTAA_1008-MFG]  (hidden comment: TFM252012ALMAR47MTAA)
L19  Ind_H: 470nH  [FP-TFM252012ALMAR47MTAA_1008-MFG]  (hidden comment: TFM252012ALMAR47MTAA)
L21  Ind_H: 470nH  [FP-TFM252012ALMAR47MTAA_1008-MFG]  (hidden comment: TFM252012ALMAR47MTAA)
L22  Ind_H: 470nH  [FP-TFM252012ALMAR47MTAA_1008-MFG]  (hidden comment: TFM252012ALMAR47MTAA)
R83  ValueDisplayed: 0  [0402]  (hidden comment: CRCW04020000Z0ED)
R209  ValueDisplayed: 0  [0402]  (hidden comment: CRCW04020000Z0ED)
R210  ValueDisplayed: 0  [0402]  (hidden comment: CRCW04020000Z0ED)
R218  ValueDisplayed: 0  [0402]  (hidden comment: CRCW04020000Z0ED)
R220  ValueDisplayed: 0  [0402L]  (hidden comment: CRCW04020000Z0ED)
R221  ValueDisplayed: 0  [0402]  (hidden comment: CRCW04020000Z0ED)
R223  ValueDisplayed: 0  [0402L]  (hidden comment: CRCW04020000Z0ED)
R224  ValueDisplayed: 10.0k  [0402]  (hidden comment: CRCW040210K0FKED)
R226  ValueDisplayed: 0  [0402]  (hidden comment: CRCW04020000Z0ED)
R227  ValueDisplayed: 0  [0402]  (hidden comment: CRCW04020000Z0ED)
U21  LP876242B0RQKRQ1  [RQK0032A-MFG]

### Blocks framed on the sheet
Optional: C230 C235
Optional: C199 C202 C232 C233

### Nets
1V0_A: C200.1 C201.1 C202.1 L19.2 R210.1
1V0_B: C197.1 C198.1 C199.1 L18.2 R209.1
1V2: C233.1 C234.1 C235.1 L22.2 R227.1
1V2_FILTERED: R223.2
1V8: C230.1 C231.1 C232.1 L21.2 R226.1
3V3: C77.1 C77.3 C78.1 C79.1 C86.1 C87.1 C89.1 C89.3 C213.2 C219.1 R224.2 U21.12(PVIN_B1) U21.14(PVIN_B2) U21.18(VCCA) U21.24(VIO) U21.28(PVIN_B3) U21.30(PVIN_B4)
5V: R220.2
GND: C77.2 C78.2 C79.2 C84.2 C86.2 C87.2 C89.2 C197.2 C198.2 C199.2 C200.2 C201.2 C202.2 C211.1 C213.1 C219.2 C223.1 C230.2 C231.2 C232.2 C233.2 C234.2 C235.2 U21.13(PGND) U21.19(AGND1) U21.21(AGND2)
BOOST_ENABLE: U21.26(GPIO9) ; off-sheet BOOST_ENABLE
CAN_nSTB: R221.2 ; off-sheet CAN_nSTB
ETHERNET_EN: R218.2 ; off-sheet ETHERNET_EN
FB_B1: R226.2 U21.7(FB_B1)
FB_B2: R227.2 U21.6(FB_B2)
FB_B3: R210.2 U21.23(FB_B3)
FB_B4: R209.2 U21.22(FB_B4)
FE1_CLKOUT_TO_PMIC: U21.10(GPIO5) ; off-sheet FE1_CLKOUT_TO_PMIC
PMIC_ENABLE: R83.1 U21.8(GPIO4) ; off-sheet PMIC_ENABLE
PMIC_GPIO1: R218.1 R221.1 U21.1(GPIO1) ; off-sheet PMIC_GPIO1
PMIC_nINT_OUT: R224.1 U21.9(~{INT}) ; off-sheet PMIC_nINT_OUT
PRE_REG_PG: R83.2 ; off-sheet PRE_REG_PG
SOC_nERROR_OUT: U21.16(GPIO6) ; off-sheet SOC_nERROR_OUT
SOC_nRESET_FROM_PMIC: U21.32(GPIO10) ; off-sheet SOC_nRESET_FROM_PMIC
SOC_SPIB_CS0: U21.2(GPIO2) ; off-sheet SOC_SPIB_CS0
SOC_SPIB_MISO: U21.3(GPIO3) ; off-sheet SOC_SPIB_MISO
SOC_SPIB_MOSI: U21.5(SDA_I2C1/SDI_SPI) ; off-sheet SOC_SPIB_MOSI
SOC_SPIB_SCLK: U21.4(SCL_I2C1/SCK_SPI) ; off-sheet SOC_SPIB_SCLK
SW_B1: L21.1 U21.11(SW_B1)
SW_B2: L22.1 U21.15(SW_B2)
SW_B3: L19.1 U21.27(SW_B3)
SW_B4: L18.1 U21.31(SW_B4)
VOUT_LDO: C84.1 U21.20(VOUT_LDO)
NetC211_2: C211.2 R220.1 U21.25(GPIO8)
NetC223_2: C223.2 R223.1 U21.17(GPIO7)

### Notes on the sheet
- PMIC
- (VMON1)
- (VMON2)
- Recommended to
- Reduce Ripple
- Buck 4 is NOT enabled by default.  It must be enabled over SPI.
- Write 0x33 to address 0x0A

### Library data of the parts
C77 C89 = CMP-0088247-2: 3 Terminals Low ESL Chip Multilayer Ceramic Capacitors for Automotive; Manufacturer: Murata; VDC_V: 16V; SizeZ_mm: 0.7mm; Tolerance_%: 20%; AEC Grade: Grade 1; Cap_F: 1µF; AEC Qualified: Yes
C78 C79 C86 C87 = CMP-0008017-2: CAP, CERM, 10 uF, 10 V, +/- 10%, X7R, 0805; Manufacturer: MuRata; TaMin_C: -55°C; Polarized: N; SizeAreaWB_mm2: 6.75; Value1: Unknown; U/M: EA; Value: 10uF; TaMax_C: 125°C; SizeZ_mm: 1.45; SizeX_mm: 2; SizeY_mm: 1.25; Cap_Case: 0805; SizeArea_mm2: 2.5; CompType: Capacitor; Cap_F: 10µF; AEC Category: Q200
C84 = CMP-0007134-5: CAP, CERM, 2.2 uF, 6.3 V, +/- 10%, X7R, AEC-Q200 Grade 1, 0603; Manufacturer: MuRata; TaMin_C: -55°C; Polarized: N; SizeAreaWB_mm2: 4.68; Value1: Unknown; U/M: EA; Value: 2.2uF; TaMax_C: 125°C; SizeZ_mm: 1; SizeX_mm: 1.6; SizeY_mm: 0.8; Cap_Case: 0603; SizeArea_mm2: 1.28; CompType: Capacitor; AEC Qualified: Y; AEC Category: Q200
C197-C202 C230-C235 = CMP-0008015-1: CAP, CERM, 22 uF, 6.3 V, +/- 20%, X7T, AEC-Q200 Grade 1, 0805; Manufacturer: MuRata; TaMin_C: -55°C; Polarized: N; SizeAreaWB_mm2: 6.75; Value1: Unknown; U/M: EA; Value: 22uF; TaMax_C: 125°C; SizeZ_mm: 1.45; SizeX_mm: 2; SizeY_mm: 1.25; SizeArea_mm2: 2.5; CompType: Capacitor; AEC Qualified: Y; Cap_F: 22µF; AEC Grade: 1; AEC Category: Q200
C211 C223 = CMP-0006351-2: as C153 on sheet Pre_Reg
C213 C219 = CMP-0064967-2: CAP, CERM, 0.47 uF, 10 V,+/- 10%, X7S, 0402; Manufacturer: MuRata; TaMin_C: -55°C; Polarized: N; SizeAreaWB_mm2: 3; Value1: Unknown; U/M: EA; Value: 0.47uF; TaMax_C: 125°C; SizeZ_mm: 0.6; SizeX_mm: 1; SizeY_mm: 0.5; Cap_Case: 0402; CompType: Capacitor; Cap_F: 470nF; AEC Category: Q200
L18 L19 L21 L22 = CMP-0090526-1: 470nH Shielded Thin Film Inductor 4.9A 24mOhm Max 1008 (2520 Metric); Manufacturer: TDK; Value: 0.47uH; DCR_ohm: 0.024; SizeZ_mm: 1.2mm; Test Frequency: 1MHz; Tolerance_%: 20%; Isat: 5.8A; AEC Qualified: Yes; AEC Grade: Grade 0; Shrouded: true; Material: Metal; Irms: 5.6A
R83 R209 R210 R218 R221 R226 R227 = CMP-0026822-3: as R205 on sheet Pre_Reg
R220 R223 = CMP-0026822-3: RES, 0, 5%, 0.063 W, AEC-Q200 Grade 0, 0402; Manufacturer: Vishay-Dale; Power_W: 63mW; TempCo: 200 ppm/C; Value_Code: 0000; Value: 0; EIA_Code: E24; SizeX_mm: 1; SizeY_mm: 0.5; SizeZ_mm: 0.6; Value2: 0.063W; CompType: Resistor; AEC Qualified: Y; VDC_V: 50V; AEC Category: Q200
R224 = CMP-0025958-3: as R58 on sheet Pre_Reg
U21 = CMP-0091103-2: Four-Phase, 20-A Buck Converter With Integrated Switches; Manufacturer: Texas Instruments; Output Type: AdjustableProgrammable; TaMax_C: +125°C; Output Voltage: 0.3-3.34V; Standoff Height: 0mm; Nominal Supply Current: 3uA; Switching Frequency: 2.2-4.4-8.8MHz; AEC Qualified: Yes; AEC Category: Q200; CompType: IC; SizeZ_mm: 1mm; TaMin_C: -40°C; Max Duty Cycle: 60%; Max Supply Voltage: 5.5V; TJmax_C: +150°C; Number Of Outputs: 4; AEC Grade: Grade 1; Min Supply Voltage: 2.8V

## Sheet SOC_PWR.SchDoc
size 431 x 279 mm; Date: Not shown in title block; ApprovedBy: Not shown in title block; CheckedBy: Not shown in title block; Author: Not shown in title block; CompanyName: Not shown in title block; DrawnBy: B. Shaffer; Engineer: Not shown in title block; Organization: Not shown in title block; Address1: Not shown in title block; Address2: Not shown in title block; Address3: Not shown in title block; Address4: Not shown in title block; DocumentNumber: 3; Revision: Use project parameter SCH_Rev; SheetNumber: 3; SheetTotal: 17; PageSetup: Record=PageOptions¦CenterHorizontal=True¦CenterVertical=True¦PrintScale=1.00¦XCorrection=1.00¦YCorrection=1.00¦PrintKind=0¦BorderSize=5000000¦LeftOffset=0¦BottomOffset=0¦Orientation=2¦PaperLength=1000¦PaperWidth=1000¦Scale=100¦PaperSource=15¦PrintQuality=600¦MediaType=1¦DitherType=10¦PaperKind=Letter¦PrintScaleMode=1
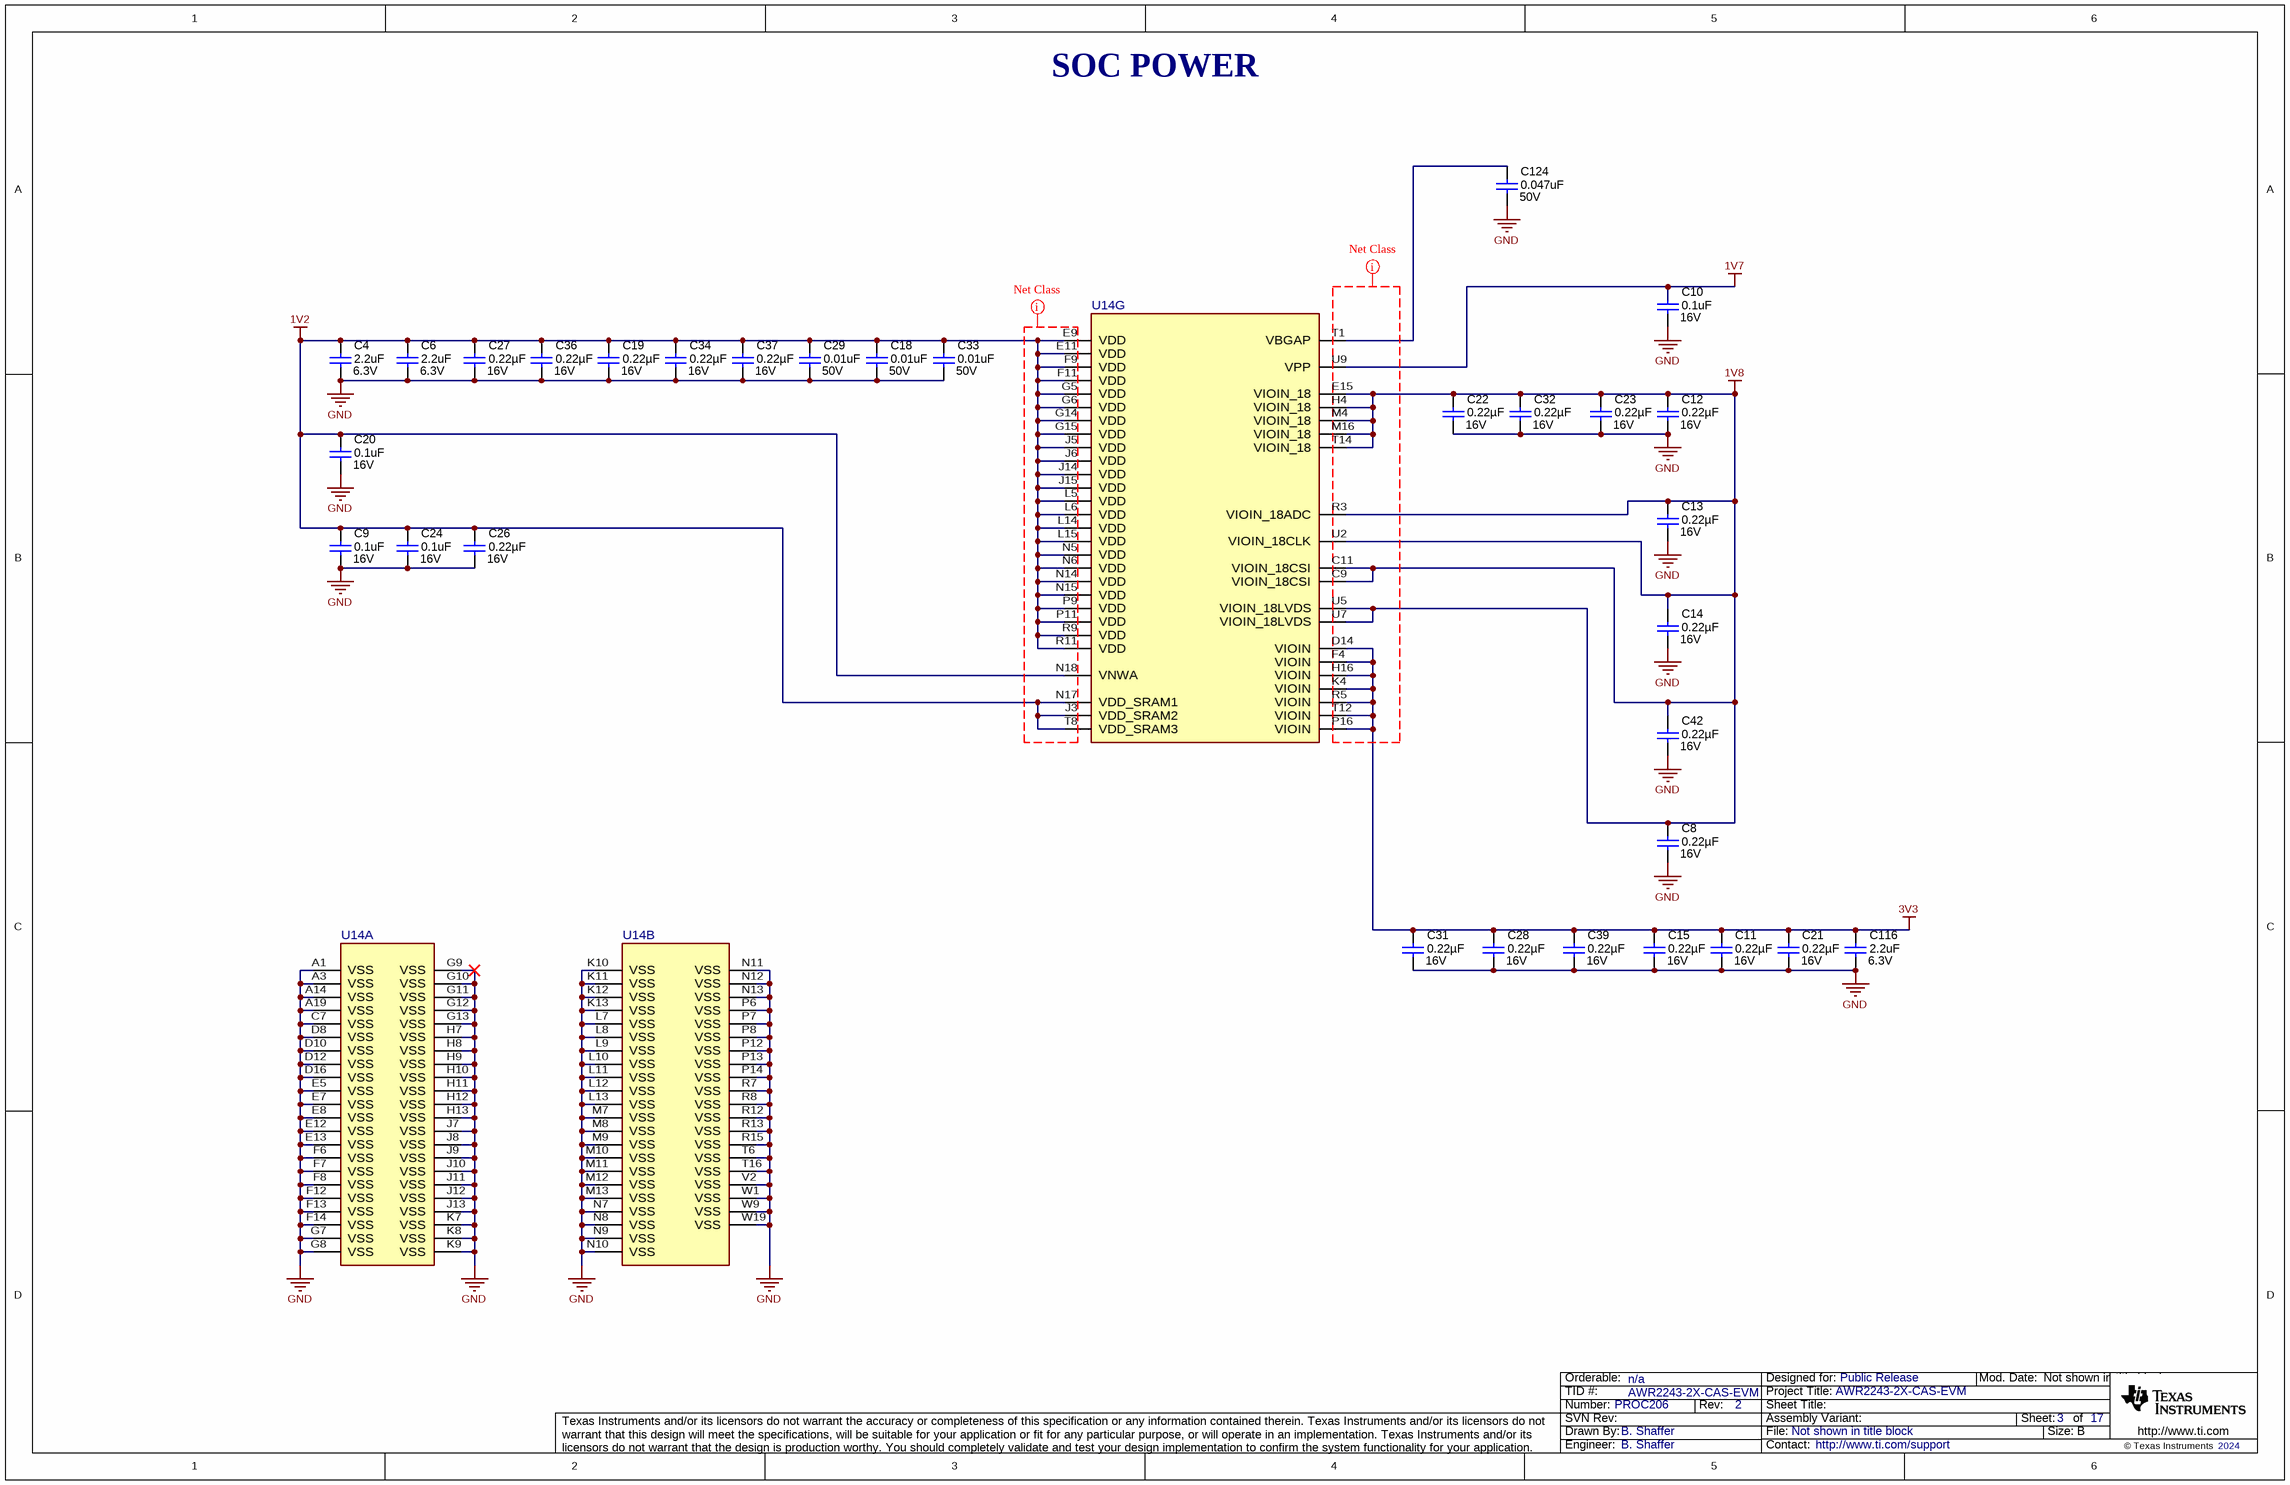
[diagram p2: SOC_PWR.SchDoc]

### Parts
(Parts that share a designator on the sheet are numbered #1, #2 ... from top to bottom, then left to right.)
C4  VDC_V: 6.3V  ValueDisplayed: 2.2uF  [0603]  (hidden comment: GCM188R70J225KE22D)
C6  VDC_V: 6.3V  ValueDisplayed: 2.2uF  [0603]  (hidden comment: GCM188R70J225KE22D)
C8  VDC_V: 16V  ValueDisplayed: 0.22µF  [0402L]  (hidden comment: GCM155R71C224KE02D)
C9  VDC_V: 16V  ValueDisplayed: 0.1uF  [0402L]  (hidden comment: GCM155R71C104KA55D)
C10  VDC_V: 16V  ValueDisplayed: 0.1uF  [0402L]  (hidden comment: GCM155R71C104KA55D)
C11  VDC_V: 16V  ValueDisplayed: 0.22µF  [0402L]  (hidden comment: GCM155R71C224KE02D)
C12  VDC_V: 16V  ValueDisplayed: 0.22µF  [0402L]  (hidden comment: GCM155R71C224KE02D)
C13  VDC_V: 16V  ValueDisplayed: 0.22µF  [0402L]  (hidden comment: GCM155R71C224KE02D)
C14  VDC_V: 16V  ValueDisplayed: 0.22µF  [0402L]  (hidden comment: GCM155R71C224KE02D)
C15  VDC_V: 16V  ValueDisplayed: 0.22µF  [0402L]  (hidden comment: GCM155R71C224KE02D)
C18  VDC_V: 50V  ValueDisplayed: 0.01uF  [0402]  (hidden comment: CGA2B3X7R1H103K050BB)
C19  VDC_V: 16V  ValueDisplayed: 0.22µF  [0402L]  (hidden comment: GCM155R71C224KE02D)
C20  VDC_V: 16V  ValueDisplayed: 0.1uF  [0402L]  (hidden comment: GCM155R71C104KA55D)
C21  VDC_V: 16V  ValueDisplayed: 0.22µF  [0402L]  (hidden comment: GCM155R71C224KE02D)
C22  VDC_V: 16V  ValueDisplayed: 0.22µF  [0402L]  (hidden comment: GCM155R71C224KE02D)
C23  VDC_V: 16V  ValueDisplayed: 0.22µF  [0402L]  (hidden comment: GCM155R71C224KE02D)
C24  VDC_V: 16V  ValueDisplayed: 0.1uF  [0402L]  (hidden comment: GCM155R71C104KA55D)
C26  VDC_V: 16V  ValueDisplayed: 0.22µF  [0402L]  (hidden comment: GCM155R71C224KE02D)
C27  VDC_V: 16V  ValueDisplayed: 0.22µF  [0402L]  (hidden comment: GCM155R71C224KE02D)
C28  VDC_V: 16V  ValueDisplayed: 0.22µF  [0402L]  (hidden comment: GCM155R71C224KE02D)
C29  VDC_V: 50V  ValueDisplayed: 0.01uF  [0402]  (hidden comment: CGA2B3X7R1H103K050BB)
C31  VDC_V: 16V  ValueDisplayed: 0.22µF  [0402L]  (hidden comment: GCM155R71C224KE02D)
C32  VDC_V: 16V  ValueDisplayed: 0.22µF  [0402L]  (hidden comment: GCM155R71C224KE02D)
C33  VDC_V: 50V  ValueDisplayed: 0.01uF  [0402]  (hidden comment: CGA2B3X7R1H103K050BB)
C34  VDC_V: 16V  ValueDisplayed: 0.22µF  [0402L]  (hidden comment: GCM155R71C224KE02D)
C36  VDC_V: 16V  ValueDisplayed: 0.22µF  [0402L]  (hidden comment: GCM155R71C224KE02D)
C37  VDC_V: 16V  ValueDisplayed: 0.22µF  [0402L]  (hidden comment: GCM155R71C224KE02D)
C39  VDC_V: 16V  ValueDisplayed: 0.22µF  [0402L]  (hidden comment: GCM155R71C224KE02D)
C42  VDC_V: 16V  ValueDisplayed: 0.22µF  [0402L]  (hidden comment: GCM155R71C224KE02D)
C116  VDC_V: 6.3V  ValueDisplayed: 2.2uF  [0603]  (hidden comment: GCM188R70J225KE22D)
C124  VDC_V: 50V  ValueDisplayed: 0.047uF  [0402]  (hidden comment: CGA2B3X7R1H473K050BB)
U14#1  AM2732ADRFGQZCERQ1  [ZCE0285A-MFG]  (value not drawn)  (part G of 7)
U14#2  AM2732ADRFGQZCERQ1  [ZCE0285A-MFG]  (value not drawn)  (parts A,B of 7)

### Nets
1V2: C4.2 C6.2 C9.2 C18.1 C19.2 C20.2 C24.2 C26.2 C27.2 C29.1 C33.1 C34.2 C36.2 C37.2 U14#1.E9(VDD) U14#1.E11(VDD) U14#1.F9(VDD) U14#1.F11(VDD) U14#1.G5(VDD) U14#1.G6(VDD) U14#1.G14(VDD) U14#1.G15(VDD) U14#1.J3(VDD_SRAM2) U14#1.J5(VDD) U14#1.J6(VDD) U14#1.J14(VDD) U14#1.J15(VDD) U14#1.L5(VDD) U14#1.L6(VDD) U14#1.L14(VDD) U14#1.L15(VDD) U14#1.N5(VDD) U14#1.N6(VDD) U14#1.N14(VDD) U14#1.N15(VDD) U14#1.N17(VDD_SRAM1) U14#1.N18(VNWA) U14#1.P9(VDD) U14#1.P11(VDD) U14#1.R9(VDD) U14#1.R11(VDD) U14#1.T8(VDD_SRAM3)
1V7: C10.2 U14#1.U9(VPP)
1V8: C8.2 C12.2 C13.2 C14.2 C22.2 C23.2 C32.2 C42.2 U14#1.C9(VIOIN_18CSI) U14#1.C11(VIOIN_18CSI) U14#1.E15(VIOIN_18) U14#1.H4(VIOIN_18) U14#1.M4(VIOIN_18) U14#1.M16(VIOIN_18) U14#1.R3(VIOIN_18ADC) U14#1.T14(VIOIN_18) U14#1.U2(VIOIN_18CLK) U14#1.U5(VIOIN_18LVDS) U14#1.U7(VIOIN_18LVDS)
3V3: C11.2 C15.2 C21.2 C28.2 C31.2 C39.2 C116.2 U14#1.D14(VIOIN) U14#1.F4(VIOIN) U14#1.H16(VIOIN) U14#1.K4(VIOIN) U14#1.P16(VIOIN) U14#1.R5(VIOIN) U14#1.T12(VIOIN)
GND: C4.1 C6.1 C8.1 C9.1 C10.1 C11.1 C12.1 C13.1 C14.1 C15.1 C18.2 C19.1 C20.1 C21.1 C22.1 C23.1 C24.1 C26.1 C27.1 C28.1 C29.2 C31.1 C32.1 C33.2 C34.1 C36.1 C37.1 C39.1 C42.1 C116.1 C124.2 U14#2.A1(VSS) U14#2.A3(VSS) U14#2.A14(VSS) U14#2.A19(VSS) U14#2.C7(VSS) U14#2.D8(VSS) U14#2.D10(VSS) U14#2.D12(VSS) U14#2.D16(VSS) U14#2.E5(VSS) U14#2.E7(VSS) U14#2.E8(VSS) U14#2.E12(VSS) U14#2.E13(VSS) U14#2.F6(VSS) U14#2.F7(VSS) U14#2.F8(VSS) U14#2.F12(VSS) U14#2.F13(VSS) U14#2.F14(VSS) U14#2.G7(VSS) U14#2.G8(VSS) U14#2.G9(VSS) U14#2.G10(VSS) U14#2.G11(VSS) U14#2.G12(VSS) U14#2.G13(VSS) U14#2.H7(VSS) U14#2.H8(VSS) U14#2.H9(VSS) U14#2.H10(VSS) U14#2.H11(VSS) U14#2.H12(VSS) U14#2.H13(VSS) U14#2.J7(VSS) U14#2.J8(VSS) U14#2.J9(VSS) U14#2.J10(VSS) U14#2.J11(VSS) U14#2.J12(VSS) U14#2.J13(VSS) U14#2.K7(VSS) U14#2.K8(VSS) U14#2.K9(VSS) U14#2.K10(VSS) U14#2.K11(VSS) U14#2.K12(VSS) U14#2.K13(VSS) U14#2.L7(VSS) U14#2.L8(VSS) U14#2.L9(VSS) U14#2.L10(VSS) U14#2.L11(VSS) U14#2.L12(VSS) U14#2.L13(VSS) U14#2.M7(VSS) U14#2.M8(VSS) U14#2.M9(VSS) U14#2.M10(VSS) U14#2.M11(VSS) U14#2.M12(VSS) U14#2.M13(VSS) U14#2.N7(VSS) U14#2.N8(VSS) U14#2.N9(VSS) U14#2.N10(VSS) U14#2.N11(VSS) U14#2.N12(VSS) U14#2.N13(VSS) U14#2.P6(VSS) U14#2.P7(VSS) U14#2.P8(VSS) U14#2.P12(VSS) U14#2.P13(VSS) U14#2.P14(VSS) U14#2.R7(VSS) U14#2.R8(VSS) U14#2.R12(VSS) U14#2.R13(VSS) U14#2.R15(VSS) U14#2.T6(VSS) U14#2.T16(VSS) U14#2.V2(VSS) U14#2.W1(VSS) U14#2.W9(VSS) U14#2.W19(VSS)
NetC124_1: C124.1 U14#1.T1(VBGAP)

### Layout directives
net class SOC_PWR: (no net found under the mark)

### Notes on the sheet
- SOC POWER

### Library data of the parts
C4 C6 C116 = CMP-0007134-5: CAP, CERM, 2.2 uF, 6.3 V, +/- 10%, X7R, AEC-Q200 Grade 1, 0603; Manufacturer: MuRata; TaMin_C: -55°C; Polarized: N; SizeAreaWB_mm2: 4.68; Value1: Unknown; U/M: EA; Value: 2.2uF; TaMax_C: 125°C; SizeZ_mm: 1; SizeX_mm: 1.6; SizeY_mm: 0.8; SizeArea_mm2: 1.28; CompType: Capacitor; AEC Qualified: Y; Cap_F: 2.2µF; AEC Category: Q200
C8 C11-C15 C19 C21-C23 C26-C28 C31 C32 C34 C36 C37 C39 C42 = CMP-0078265-1: CAP, CERM, 0.22 µF, 16 V,+/- 10%, X7R, AEC-Q200 Grade 1, 0402; Manufacturer: MuRata; TaMin_C: -55°C; Polarized: N; SizeAreaWB_mm2: 3; U/M: EA; Value: 0.22uF; TaMax_C: 125°C; SizeZ_mm: 0.6; SizeX_mm: 1; SizeY_mm: 0.5; Cap_Case: 0402; CompType: Capacitor; AEC Qualified: Y; Cap_F: 220nF; AEC Category: Q200
C9 C10 C20 C24 = CMP-0006351-2: as C153 on sheet Pre_Reg
C18 C29 C33 = CMP-0006324-2: CAP, CERM, 0.01 uF, 50 V, +/- 10%, X7R, AEC-Q200 Grade 1, 0402; Manufacturer: TDK; TaMin_C: -55°C; ESR_ohm: 0.333065; Polarized: N; SizeAreaWB_mm2: 3; Value1: 0.333065 ohm; U/M: EA; Value: 0.01uF; TaMax_C: 125°C; SizeZ_mm: 0.6; SizeX_mm: 1; SizeY_mm: 0.5; CompType: Capacitor; AEC Qualified: Y; Cap_F: 10nF; IRMS_A: 323.373mA; AEC Category: Q200
C124 = CMP-0006330-2: CAP, CERM, 0.047 uF, 50 V, +/- 10%, X7R, AEC-Q200 Grade 1, 0402; Manufacturer: TDK; TaMin_C: -55°C; ESR_ohm: 0.06407; Polarized: N; SizeAreaWB_mm2: 3; Value1: 0.06407 ohm; U/M: EA; TaMax_C: 125°C; SizeZ_mm: 0.6; SizeX_mm: 1; SizeY_mm: 0.5; CompType: Capacitor; AEC Qualified: Y; Cap_F: 47nF; IRMS_A: 646.122mA; AEC Category: Q200
U14#1 U14#2 = CMP-0088502-3: No description; Manufacturer: Texas Instruments; SizeZ_mm: 1.3mm; Number Of Uart Channels: 2; Standoff Height: 0.23mm; Number Of A/D Converters: 1; CompType: IC; Number Of Pwm Channels: 3; Number Of Adc Channels: 9; AEC Category: Q200; Interface: I2C,SPI,UART,CAN,Ethernet,LVDS,Other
